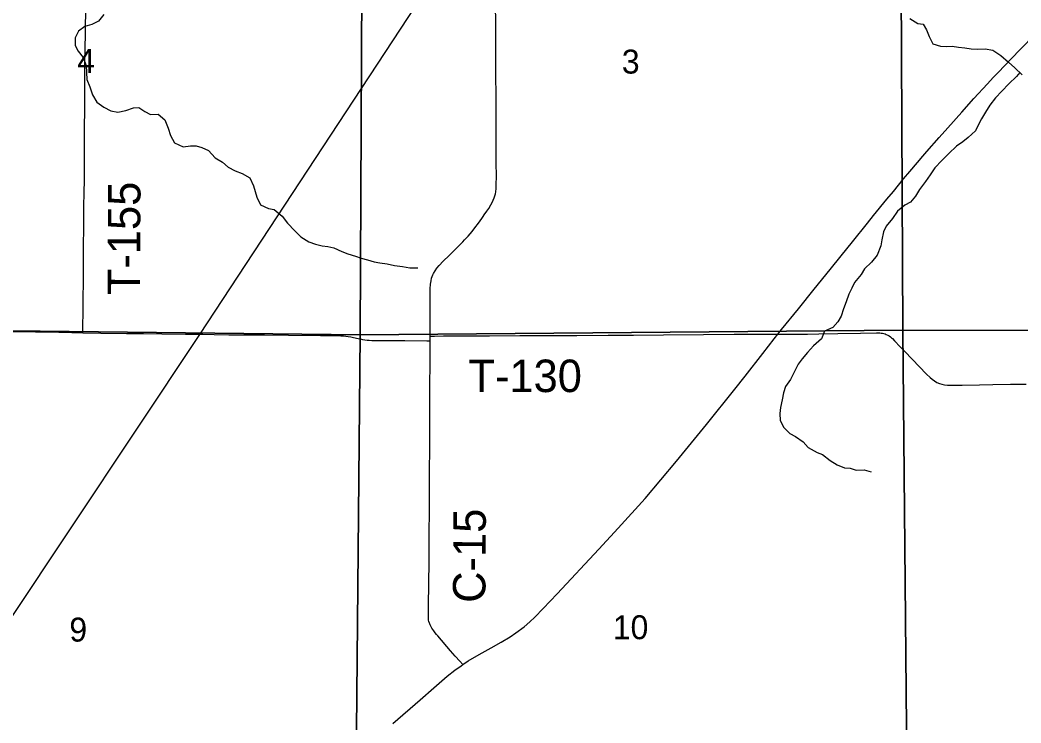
# Model space of a CAD drawing. Extents: x 0 to 34, y 0 to 22.
# Drawn here: x 4.964 to 5.839, y 16.916 to 17.53 of the extents above; entities that cross this region are included whole.
import ezdxf

# ---------------------------------------------------------------- set-up
doc = ezdxf.new("R2010")
doc.units = 0
for name, color, linetype in [('GM_X_Corporation', 7, 'Continuous'), ('GM_X_County_Road', 7, 'Continuous'), ('GM_X_County_Road_Text', 7, 'Continuous'), ('GM_X_Minor_River', 7, 'Continuous'), ('GM_X_Rail_Line', 7, 'Continuous'), ('GM_X_Section_Text', 7, 'Continuous'), ('GM_X_State_Route', 7, 'Continuous'), ('GM_X_Township_Road', 7, 'Continuous'), ('GM_X_Township_Road_Text', 7, 'Continuous')]:
    doc.layers.add(name, color=color, linetype=linetype)

msp = doc.modelspace()

# ---------------------------------------------------------------- linework, layer by layer
at = {"layer": 'GM_X_Corporation'}
for points in [[(5.73364, 17.74138), (6.21312, 17.75585), (6.2055, 17.25889), (5.73597, 17.25914)], [(5.26362, 17.74328), (5.26124, 17.2552), (4.77754, 17.26078), (4.78425, 17.74522), (5.23463, 17.74294)], [(5.73061, 17.74103), (5.73364, 17.74138), (5.73597, 17.25914), (5.26124, 17.2552), (5.26362, 17.74328)], [(4.77754, 17.26078), (5.26124, 17.2552), (5.25664, 16.75179), (4.76416, 16.74758)], [(5.26124, 17.2552), (5.73597, 17.25914), (5.7408, 16.75434), (5.25664, 16.75179)], [(5.73597, 17.25914), (6.2055, 17.25889), (6.22077, 16.758), (5.7408, 16.75434)]]:
    msp.add_lwpolyline(points, close=True, dxfattribs=at)
at = {"layer": 'GM_X_County_Road'}
for points in [[(5.38002, 17.5113), (5.37998, 17.52468), (5.37988, 17.54673)], [(5.38027, 17.46194), (5.38027, 17.46346), (5.38011, 17.48273), (5.38008, 17.49049), (5.38002, 17.5113)], [(5.32263, 17.25404), (5.32267, 17.26889), (5.32271, 17.28068), (5.32275, 17.29532), (5.32295, 17.29939), (5.32338, 17.30252), (5.32383, 17.30467), (5.3249, 17.30764), (5.32544, 17.30879), (5.3269, 17.31123), (5.32858, 17.31352), (5.33061, 17.31593), (5.33405, 17.31956), (5.3391, 17.32464), (5.34623, 17.33158), (5.34933, 17.33461), (5.35127, 17.3366), (5.35277, 17.33816), (5.35383, 17.33929), (5.35592, 17.34155), (5.35756, 17.3434), (5.35935, 17.34553), (5.36181, 17.3487), (5.36493, 17.35295), (5.36781, 17.357), (5.36886, 17.35854), (5.36996, 17.36005), (5.37222, 17.36338), (5.37379, 17.36567), (5.37575, 17.3688), (5.37689, 17.37096), (5.37778, 17.37281), (5.37865, 17.37496), (5.37926, 17.37677), (5.37962, 17.37841), (5.37992, 17.38028), (5.38021, 17.38321), (5.38042, 17.38703), (5.38053, 17.39323), (5.38053, 17.39602), (5.38048, 17.40347), (5.38042, 17.41436), (5.38028, 17.43518), (5.38024, 17.43891), (5.38026, 17.45383), (5.38027, 17.46194)], [(5.32262, 17.24996), (5.32263, 17.25178), (5.32263, 17.25404)], [(5.35114, 16.96691), (5.34857, 16.96974), (5.34439, 16.97433), (5.34053, 16.97877), (5.32919, 16.99188), (5.32809, 16.99324), (5.32709, 16.9946), (5.32587, 16.99623), (5.32488, 16.99764), (5.32418, 16.99873), (5.32349, 16.99986), (5.32262, 17.00153), (5.3222, 17.00242), (5.3219, 17.00319), (5.3215, 17.00441), (5.32125, 17.00567), (5.32113, 17.0068), (5.32109, 17.00813), (5.32109, 17.0101), (5.32113, 17.01184), (5.32126, 17.02442), (5.32133, 17.03169), (5.32167, 17.06277), (5.32182, 17.08391), (5.32193, 17.09883), (5.32203, 17.10908), (5.32199, 17.12401), (5.32211, 17.13924), (5.32226, 17.1526), (5.3223, 17.17654), (5.32243, 17.20637), (5.32255, 17.23445), (5.32262, 17.24996)]]:
    msp.add_lwpolyline(points, dxfattribs=at)
at = {"layer": 'GM_X_Minor_River'}
for points in [[(5.03708, 17.53531), (5.0325, 17.52945), (5.02661, 17.52645), (5.02054, 17.52477), (5.01502, 17.52082), (5.01196, 17.51476), (5.0121, 17.50831), (5.01453, 17.50336), (5.01905, 17.49764), (5.02165, 17.49079), (5.02199, 17.48452), (5.02233, 17.47844), (5.02476, 17.47197), (5.02718, 17.46513), (5.03092, 17.45865), (5.03715, 17.45425), (5.04338, 17.45098), (5.04943, 17.44981), (5.05645, 17.45148), (5.06309, 17.45371), (5.06783, 17.45407), (5.07311, 17.45043), (5.07802, 17.44774), (5.08465, 17.44827), (5.09049, 17.4433), (5.09347, 17.43588), (5.09552, 17.42941), (5.09889, 17.42294), (5.10644, 17.41948), (5.11289, 17.42058), (5.118, 17.42055), (5.12291, 17.419), (5.12877, 17.41631), (5.13441, 17.41001), (5.14083, 17.40618), (5.14591, 17.40178), (5.15196, 17.39871), (5.15819, 17.3962), (5.16479, 17.39237), (5.16797, 17.38532), (5.16946, 17.38057), (5.17094, 17.37562), (5.17412, 17.36896), (5.18111, 17.3655), (5.18621, 17.36471), (5.193, 17.35898), (5.19788, 17.35287), (5.20409, 17.34619), (5.20936, 17.34085), (5.21634, 17.33663), (5.22239, 17.33432), (5.22806, 17.33295), (5.23298, 17.33254), (5.23828, 17.33118), (5.24546, 17.3281), (5.25056, 17.32599), (5.25736, 17.32405), (5.26228, 17.32231), (5.26776, 17.32076)], [(5.74234, 17.5317), (5.74912, 17.52749), (5.75404, 17.52689), (5.75685, 17.52195), (5.75927, 17.51606), (5.76226, 17.50959), (5.76906, 17.50747), (5.77417, 17.50725), (5.77927, 17.5076), (5.78476, 17.50681), (5.79043, 17.50602), (5.79591, 17.50523), (5.8012, 17.50501), (5.80801, 17.50516), (5.81482, 17.50418), (5.82179, 17.4994), (5.82857, 17.49367), (5.83421, 17.48871), (5.84042, 17.48261)], [(5.83839, 17.48461), (5.83549, 17.48093), (5.82883, 17.47471), (5.82274, 17.4683), (5.81722, 17.46245), (5.81208, 17.45603), (5.80845, 17.44998), (5.80501, 17.44393), (5.80233, 17.43902), (5.79965, 17.43353), (5.79338, 17.42769), (5.78863, 17.42392), (5.78312, 17.42016), (5.77627, 17.41375), (5.77037, 17.40772), (5.76409, 17.40131), (5.75989, 17.39507), (5.75589, 17.38922), (5.75074, 17.38223), (5.74711, 17.37637), (5.74292, 17.37108), (5.73799, 17.36865), (5.73134, 17.36318), (5.72695, 17.35695), (5.72161, 17.35034), (5.71931, 17.34524), (5.71776, 17.33823), (5.71678, 17.33293), (5.71371, 17.32479), (5.70857, 17.31875), (5.70267, 17.3129), (5.69961, 17.30799), (5.6939, 17.30101), (5.69141, 17.2959), (5.68873, 17.29061), (5.68642, 17.28398), (5.68412, 17.27793), (5.68219, 17.27149), (5.67913, 17.26658), (5.67494, 17.26167), (5.66755, 17.25849), (5.66486, 17.25168), (5.65801, 17.24546), (5.65268, 17.23961), (5.64811, 17.23432), (5.64468, 17.22941), (5.64105, 17.22261), (5.63798, 17.21599), (5.6336, 17.20994), (5.63167, 17.20445), (5.63069, 17.19839), (5.62914, 17.19176), (5.62854, 17.18627), (5.6287, 17.18039), (5.63187, 17.17411), (5.63733, 17.16896), (5.64223, 17.16628), (5.64883, 17.16169), (5.65334, 17.15655), (5.66107, 17.15233), (5.66598, 17.1506), (5.67257, 17.14544), (5.6786, 17.14162), (5.68502, 17.13893), (5.68993, 17.13852), (5.69522, 17.13697), (5.70241, 17.13712), (5.70845, 17.13538)], [(5.26776, 17.32076), (5.27362, 17.31902), (5.27854, 17.31823), (5.28497, 17.31724), (5.2914, 17.31568), (5.29841, 17.31507), (5.30484, 17.3139), (5.31185, 17.31386)]]:
    msp.add_lwpolyline(points, dxfattribs=at)
at = {"layer": 'GM_X_Rail_Line'}
msp.add_lwpolyline([(4.83086, 16.81428), (4.95348, 17.00356), (5.121, 17.25544), (5.31678, 17.55326), (5.45252, 17.7592), (5.58679, 17.98275), (5.74825, 18.23979), (5.90418, 18.49744), (6.02127, 18.68264), (6.13663, 18.87252), (6.2288, 19.01731), (6.34315, 19.20099), (6.38785, 19.27035), (6.55501, 19.53303), (6.71382, 19.79395), (6.76349, 19.87076), (6.84474, 20.00352), (6.94083, 20.16003), (7.03262, 20.3087), (7.17305, 20.5257), (7.19919, 20.56539)], dxfattribs=at)
at = {"layer": 'GM_X_State_Route'}
for points in [[(5.70522, 17.35292), (5.71052, 17.35958), (5.72216, 17.37375), (5.72789, 17.3806), (5.73225, 17.38603), (5.73669, 17.39154), (5.74211, 17.39795), (5.74883, 17.40573), (5.75371, 17.41137), (5.75709, 17.41543), (5.76792, 17.42786), (5.77536, 17.43622), (5.78759, 17.44987), (5.79835, 17.46179), (5.81027, 17.47478), (5.81521, 17.48005), (5.82038, 17.48548), (5.82449, 17.48984), (5.83854, 17.50437), (5.85223, 17.51837)], [(5.28986, 16.91527), (5.31386, 16.93598), (5.32569, 16.94646), (5.33745, 16.9566), (5.34428, 16.96204), (5.34958, 16.96589), (5.35114, 16.96691), (5.35583, 16.96999), (5.36548, 16.97569), (5.37611, 16.98152), (5.38479, 16.98637), (5.39245, 16.99107), (5.39758, 16.99454), (5.40472, 16.99999), (5.40967, 17.00416), (5.41414, 17.0083), (5.42156, 17.01576), (5.43363, 17.02871), (5.47003, 17.06788), (5.48695, 17.0861), (5.51065, 17.11201), (5.53825, 17.14482), (5.56169, 17.17343), (5.56431, 17.17664), (5.58921, 17.20753), (5.59828, 17.21898), (5.61365, 17.2389), (5.62349, 17.25174), (5.62663, 17.25571), (5.62986, 17.25979), (5.64475, 17.27801), (5.6586, 17.29512), (5.67248, 17.31239), (5.68212, 17.32419), (5.69214, 17.33646), (5.70522, 17.35292)]]:
    msp.add_lwpolyline(points, dxfattribs=at)
at = {"layer": 'GM_X_Township_Road'}
for points in [[(5.01888, 17.25702), (5.01896, 17.28086), (5.01944, 17.30762), (5.01943, 17.3303), (5.01964, 17.35141), (5.01975, 17.36746), (5.01986, 17.37957), (5.02008, 17.39045), (5.02018, 17.41034), (5.02057, 17.47818), (5.02058, 17.49183), (5.02093, 17.51898), (5.02137, 17.54303), (5.02154, 17.56086), (5.02153, 17.57863), (5.02177, 17.59469), (5.02174, 17.60587), (5.022, 17.62512), (5.02213, 17.63546), (5.02223, 17.64356), (5.02251, 17.66789), (5.02296, 17.70399), (5.02308, 17.7441)], [(4.95706, 17.25819), (4.99777, 17.25748), (5.00926, 17.25721), (5.01888, 17.25702)], [(5.01888, 17.25702), (5.03443, 17.25671), (5.0568, 17.25647), (5.07171, 17.25621), (5.08787, 17.25602), (5.10869, 17.25568), (5.1236, 17.25566), (5.13355, 17.25546), (5.1466, 17.25529), (5.17767, 17.25507), (5.1988, 17.25478), (5.22676, 17.25465), (5.23921, 17.2546), (5.2445, 17.25445), (5.24678, 17.25428), (5.24887, 17.25409), (5.2509, 17.25381), (5.2532, 17.25344), (5.25553, 17.25299), (5.25962, 17.25197), (5.26158, 17.25154), (5.26342, 17.25114), (5.26539, 17.25083), (5.26755, 17.25056), (5.26933, 17.25041), (5.27143, 17.25025), (5.27333, 17.25018), (5.28022, 17.25009), (5.30035, 17.25008), (5.3196, 17.24998), (5.32262, 17.24996)], [(5.32262, 17.24996), (5.32263, 17.25178), (5.32263, 17.25404)], [(5.32263, 17.25404), (5.32636, 17.25409), (5.33414, 17.25418), (5.35901, 17.25433), (5.37454, 17.25429), (5.40096, 17.25452), (5.42116, 17.25465), (5.451, 17.25462), (5.47835, 17.2548), (5.50038, 17.25497), (5.5268, 17.25517), (5.5616, 17.25536), (5.58863, 17.25565), (5.61782, 17.25581), (5.62663, 17.25571)], [(5.62663, 17.25571), (5.63579, 17.25562), (5.65281, 17.25585), (5.66254, 17.25608), (5.67931, 17.25632), (5.69919, 17.25672), (5.71319, 17.25698), (5.71469, 17.25693), (5.71602, 17.25683), (5.7172, 17.25674), (5.71827, 17.25658), (5.71945, 17.25636), (5.72067, 17.25594), (5.72167, 17.25556), (5.72303, 17.25489), (5.72418, 17.25422), (5.72518, 17.25352), (5.7263, 17.25256), (5.7271, 17.25187), (5.72886, 17.25007), (5.73372, 17.24482), (5.73566, 17.2428), (5.73763, 17.24081), (5.7445, 17.23363), (5.75026, 17.22752), (5.75676, 17.22086), (5.75989, 17.21787), (5.76176, 17.21627), (5.76373, 17.21484), (5.76584, 17.21362), (5.76807, 17.21264), (5.77009, 17.21197), (5.77247, 17.21144), (5.7752, 17.21112), (5.77827, 17.21104), (5.78788, 17.2112), (5.80312, 17.21153), (5.81493, 17.21169), (5.83016, 17.21191), (5.84414, 17.21209)]]:
    msp.add_lwpolyline(points, dxfattribs=at)

# ---------------------------------------------------------------- texts
at = {"layer": 'GM_X_County_Road_Text'}
msp.add_text('C-15', height=0.028409, rotation=89.65509, dxfattribs=at).set_placement((5.37088, 17.02077))
at = {"layer": 'GM_X_Section_Text'}
for s, height, p in [('4', 0.02093, (5.01381, 17.4842)), ('3', 0.02093, (5.49027, 17.48363)), ('9', 0.02093, (5.00694, 16.98696)), ('10', 0.020928, (5.48235, 16.98904))]:
    msp.add_text(s, height=height, rotation=0.00001, dxfattribs=at).set_placement(p)
at = {"layer": 'GM_X_Township_Road_Text'}
for s, rotation, p in [('T-155', 89.72394, (5.06875, 17.28981)), ('T-130', 0.00001, (5.3561, 17.20512))]:
    msp.add_text(s, height=0.028409, rotation=rotation, dxfattribs=at).set_placement(p)

doc.saveas('drawing.dxf')
